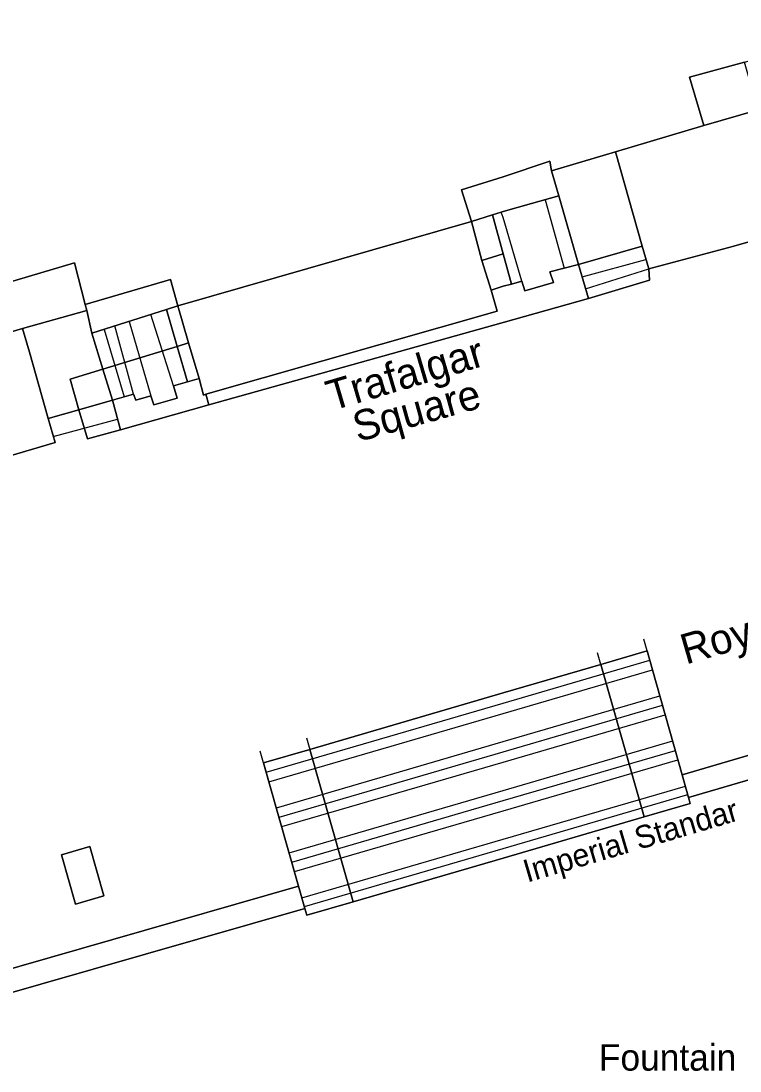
# Model space of a CAD drawing. Extents: x 529240 to 530363, y 179600 to 180767.
# Drawn here: x 529968 to 530015.7, y 180462.4 to 180532 of the extents above; entities that cross this region are included whole.
import ezdxf

# ---------------------------------------------------------------- set-up
doc = ezdxf.new("R2010")
doc.units = 0
for name, color, linetype in [('Building', 7, 'Continuous'), ('General surface', 7, 'Continuous'), ('Path', 7, 'Continuous'), ('Structure', 7, 'Continuous'), ('Unclassified', 7, 'Continuous')]:
    doc.layers.add(name, color=color, linetype=linetype)

msp = doc.modelspace()

# ---------------------------------------------------------------- linework, layer by layer
at = {"layer": 'Building'}
for points in [[(529961.6, 180513), (529971.6, 180515.95), (529972.3, 180513.2), (529977.95, 180514.85), (529978.45, 180513.1), (529997.9, 180518.7), (529997.25, 180520.8), (530000, 180521.65), (530003.1, 180522.7), (530003.2, 180522.05), (530007.45, 180523.3), (530013.3, 180525.05), (530012.35, 180528.25), (530016, 180529.25), (530019.45, 180530.2), (530023.1, 180531.2), (530023.25, 180530.75), (530033.2, 180533.75)], [(530013.3, 180525.05), (530012.35, 180528.25), (530016, 180529.25)], [(530007.45, 180523.3), (530013.3, 180525.05)], [(530003.2, 180522.05), (530007.45, 180523.3)], [(529997.9, 180518.7), (529997.25, 180520.8), (530000, 180521.65), (530003.1, 180522.7), (530003.2, 180522.05)], [(529978.45, 180513.1), (529997.9, 180518.7)], [(529998.6, 180516.1), (529997.9, 180518.7)], [(529961.6, 180513), (529971.6, 180515.95), (529972.3, 180513.2)], [(529999.2, 180514.15), (529998.6, 180516.1)], [(529972.3, 180513.2), (529977.95, 180514.85), (529978.45, 180513.1)], [(529980.3, 180507.25), (529999.6, 180512.75), (529999.2, 180514.15)], [(529972.4, 180512.8), (529972.3, 180513.2)], [(529968.15, 180511.6), (529972.4, 180512.8)], [(529978.45, 180513.1), (529979.15, 180510.65)], [(529962.5, 180509.95), (529968.15, 180511.6)], [(529979.15, 180510.65), (529979.85, 180508.3)], [(529979.85, 180508.3), (529980.15, 180507.2), (529980.3, 180507.25)]]:
    msp.add_lwpolyline(points, dxfattribs=at)
for points in [[(530016, 180529.25), (530012.35, 180528.25), (530013.3, 180525.05), (530016.9, 180526.1)], [(529979.85, 180508.3), (529980.15, 180507.2), (529980.3, 180507.25), (529999.6, 180512.75), (529999.2, 180514.15), (529998.6, 180516.1), (529997.9, 180518.7), (529978.45, 180513.1), (529979.15, 180510.65)], [(529962.5, 180509.95), (529968.15, 180511.6), (529972.4, 180512.8), (529972.3, 180513.2), (529971.6, 180515.95), (529961.6, 180513)], [(529970.73, 180476.74), (529971.66, 180473.47), (529973.53, 180474.02), (529972.6, 180477.29)]]:
    msp.add_lwpolyline(points, close=True, dxfattribs=at)
at = {"layer": 'General surface'}
for points in [[(530009.65, 180515.55), (530015.3, 180517.05), (530019.3, 180518.2), (530016.9, 180526.1), (530013.3, 180525.05), (530007.45, 180523.3), (530009.22, 180517.06)], [(530003.7, 180520.4), (530005, 180515.85), (530009.22, 180517.06), (530007.45, 180523.3), (530003.2, 180522.05)], [(529997.9, 180518.7), (529999.3, 180519.14), (529999.88, 180519.31), (530000, 180519.35), (530001.88, 180519.88), (530003.7, 180520.4), (530003.2, 180522.05), (530003.1, 180522.7), (530000, 180521.65), (529997.25, 180520.8)], [(530000, 180516.55), (530000.55, 180514.55), (530001.25, 180514.75), (530001.45, 180514.1), (530003.35, 180514.65), (530003.1, 180515.35), (530005, 180515.85), (530003.7, 180520.4), (530001.88, 180519.88), (530000, 180519.35), (529999.88, 180519.31), (529999.3, 180519.14)], [(529998.6, 180516.1), (530000, 180516.55), (529999.3, 180519.14), (529997.9, 180518.7)], [(530005, 180515.85), (530005.65, 180513.6), (530009.7, 180514.8), (530009.65, 180515.55), (530009.22, 180517.06)], [(529998.6, 180516.1), (529999.2, 180514.15), (530000, 180514.4), (530000.55, 180514.55), (530000, 180516.55)], [(529999.2, 180514.15), (529999.6, 180512.75), (529980.3, 180507.25), (529980.5, 180506.55), (530000, 180512), (530005.65, 180513.6), (530005, 180515.85), (530003.1, 180515.35), (530003.35, 180514.65), (530001.45, 180514.1), (530001.25, 180514.75), (530000.55, 180514.55), (530000, 180514.4)], [(529977.68, 180512.86), (529978.45, 180513.1), (529977.95, 180514.85), (529972.3, 180513.2), (529972.4, 180512.8), (529972.75, 180511.3)], [(529969.85, 180505.65), (529971.89, 180506.23), (529971.3, 180508.25), (529973.47, 180508.91), (529972.75, 180511.3), (529972.4, 180512.8), (529968.15, 180511.6), (529968.6, 180510.05)], [(529978.39, 180510.42), (529977.68, 180512.86), (529972.75, 180511.3), (529973.47, 180508.91)], [(529978.39, 180510.42), (529979.15, 180510.65), (529978.45, 180513.1), (529977.68, 180512.86)], [(529962.5, 180509.95), (529958.8, 180508.9), (529961.1, 180501.35), (529970.3, 180504.05), (529969.85, 180505.65), (529968.6, 180510.05), (529968.15, 180511.6)], [(529975.5, 180507.25), (529975.65, 180506.85), (529976.65, 180507.15), (529976.85, 180506.55), (529978.4, 180507), (529978.15, 180507.8), (529979.08, 180508.07), (529978.39, 180510.42), (529973.47, 180508.91), (529974.1, 180506.85)], [(529979.15, 180510.65), (529978.39, 180510.42), (529979.08, 180508.07), (529979.85, 180508.3)], [(529974.1, 180506.85), (529973.47, 180508.91), (529971.3, 180508.25), (529971.89, 180506.23)], [(529974.1, 180506.85), (529974.65, 180504.9), (529980.5, 180506.55), (529980.3, 180507.25), (529980.15, 180507.2), (529979.85, 180508.3), (529979.08, 180508.07), (529978.15, 180507.8), (529978.4, 180507), (529976.85, 180506.55), (529976.65, 180507.15), (529975.65, 180506.85), (529975.5, 180507.25)], [(529972.45, 180504.29), (529974.65, 180504.9), (529974.1, 180506.85), (529971.89, 180506.23)], [(530011.88, 180482.04), (530012.3, 180480.54), (530038.35, 180488.15), (530037.95, 180489.7)], [(529971.66, 180473.47), (529973.53, 180474.02), (529972.6, 180477.29), (529970.73, 180476.74)], [(529962.25, 180466.15), (529986.87, 180473.19), (529986.45, 180474.67), (529961.8, 180467.6)]]:
    msp.add_lwpolyline(points, close=True, dxfattribs=at)
for points in [[(530002.78, 180520.14), (530004.05, 180515.6)], [(530003.7, 180520.4), (530005, 180515.85)], [(530001.25, 180514.75), (530000, 180518.95), (529999.88, 180519.31)], [(530019.3, 180518.2), (530015.3, 180517.05), (530009.65, 180515.55), (530009.7, 180514.8), (530005.65, 180513.6), (530000, 180512), (529980.5, 180506.55), (529974.65, 180504.9), (529972.45, 180504.29), (529971.89, 180506.23), (529969.85, 180505.65), (529970.3, 180504.05), (529961.1, 180501.35)], [(530005, 180515.85), (530009.22, 180517.06)], [(530000, 180516.55), (530000.55, 180514.55)], [(530005.24, 180515.03), (530009.47, 180516.17)], [(530005.47, 180514.24), (530009.65, 180515.55)], [(530009.7, 180514.8), (530005.65, 180513.6)], [(529978.15, 180507.8), (529976.66, 180512.53)], [(529977.68, 180512.86), (529978.39, 180510.42)], [(529975.5, 180507.25), (529974.26, 180511.78)], [(529975.21, 180512.08), (529976.65, 180507.15)], [(529972.75, 180511.3), (529973.47, 180508.91)], [(529973.55, 180511.55), (529974.89, 180507.08)], [(529978.39, 180510.42), (529979.08, 180508.07)], [(529973.47, 180508.91), (529974.1, 180506.85)], [(529971.89, 180506.23), (529969.85, 180505.65)], [(529974.1, 180506.85), (529971.89, 180506.23)], [(529970.18, 180504.46), (529974.45, 180505.6)], [(529972.45, 180504.29), (529974.65, 180504.9)], [(529961.8, 180467.6), (529986.45, 180474.67), (529984.48, 180481.59), (529984.12, 180482.84), (529987.19, 180483.73), (530000, 180487.47), (530006.48, 180489.36), (530009.55, 180490.25), (530009.9, 180489), (530011.88, 180482.04), (530037.95, 180489.7)], [(530006.48, 180489.36), (530009.55, 180490.25)], [(529984.3, 180482.22), (530000, 180486.79), (530009.73, 180489.63)], [(529984.48, 180481.59), (530000, 180486.11), (530009.9, 180489)], [(529987.19, 180483.73), (530000, 180487.47), (530006.48, 180489.36)], [(530057.8, 180463.5), (530055.65, 180472), (530053.75, 180479.6), (530051.55, 180488.2), (530041.4, 180485.35), (530039.25, 180484.75), (530038.35, 180488.15), (530012.3, 180480.54), (530012.41, 180480.15), (530009.34, 180479.25), (530000, 180476.53), (529990.07, 180473.64), (529987, 180472.74), (529986.87, 180473.19), (529962.25, 180466.15)], [(529984.97, 180479.86), (530000, 180484.24), (530010.39, 180487.27)], [(529985.15, 180479.24), (530000, 180483.57), (530010.57, 180486.65)], [(529985.33, 180478.61), (530000, 180482.89), (530010.75, 180486.02)], [(529985.82, 180476.88), (530000, 180481.01), (530011.24, 180484.29)], [(529984.12, 180482.84), (529987.19, 180483.73)], [(529986, 180476.26), (530000, 180480.34), (530011.42, 180483.66)], [(529984.12, 180482.84), (529984.3, 180482.22)], [(529986.18, 180475.63), (530000, 180479.65), (530011.59, 180483.03)], [(529984.3, 180482.22), (529984.48, 180481.59)], [(529986.67, 180473.9), (530000, 180477.78), (530012.08, 180481.3)], [(529986.84, 180473.32), (530000, 180477.16), (530012.25, 180480.73)], [(530009.34, 180479.25), (530012.41, 180480.15)], [(529990.07, 180473.64), (530000, 180476.53), (530009.34, 180479.25)], [(529987, 180472.74), (529990.07, 180473.64)]]:
    msp.add_lwpolyline(points, dxfattribs=at)
at = {"layer": 'Path'}
for points in [[(530009.34, 180479.25), (530012.41, 180480.15), (530012.3, 180480.54), (530011.88, 180482.04), (530009.9, 180489), (530009.55, 180490.25), (530006.48, 180489.36)], [(530009.34, 180479.25), (530006.48, 180489.36), (530000, 180487.47), (529987.19, 180483.73), (529990.07, 180473.64), (530000, 180476.53)], [(529984.12, 180482.84), (529984.48, 180481.59), (529986.45, 180474.67), (529986.87, 180473.19), (529987, 180472.74), (529990.07, 180473.64), (529987.19, 180483.73)]]:
    msp.add_lwpolyline(points, close=True, dxfattribs=at)
at = {"layer": 'Unclassified'}
for points in [[(530013.3, 180525.05), (530016.9, 180526.1)], [(530007.45, 180523.3), (530009.22, 180517.06)], [(530003.2, 180522.05), (530003.7, 180520.4)], [(529999.88, 180519.31), (530000, 180519.35), (530001.88, 180519.88), (530003.7, 180520.4)], [(529997.9, 180518.7), (529999.3, 180519.14)], [(529999.3, 180519.14), (529999.88, 180519.31)], [(529999.3, 180519.14), (530000, 180516.55)], [(530019.3, 180518.2), (530015.3, 180517.05), (530009.65, 180515.55)], [(530009.22, 180517.06), (530009.65, 180515.55)], [(529998.6, 180516.1), (530000, 180516.55)], [(530001.25, 180514.75), (530001.45, 180514.1), (530003.35, 180514.65), (530003.1, 180515.35), (530005, 180515.85)], [(530005, 180515.85), (530005.65, 180513.6)], [(530009.65, 180515.55), (530009.7, 180514.8)], [(529999.2, 180514.15), (530000, 180514.4), (530000.55, 180514.55)], [(530000.55, 180514.55), (530001.25, 180514.75)], [(529980.5, 180506.55), (530000, 180512), (530005.65, 180513.6)], [(529972.75, 180511.3), (529972.4, 180512.8)], [(529972.75, 180511.3), (529977.68, 180512.86)], [(529977.68, 180512.86), (529978.45, 180513.1)], [(529968.15, 180511.6), (529968.6, 180510.05), (529969.85, 180505.65)], [(529978.39, 180510.42), (529973.47, 180508.91)], [(529979.15, 180510.65), (529978.39, 180510.42)], [(529973.47, 180508.91), (529971.3, 180508.25), (529971.89, 180506.23)], [(529979.08, 180508.07), (529979.85, 180508.3)], [(529978.15, 180507.8), (529979.08, 180508.07)], [(529978.4, 180507), (529978.15, 180507.8)], [(529974.1, 180506.85), (529975.5, 180507.25)], [(529975.65, 180506.85), (529975.5, 180507.25)], [(529975.65, 180506.85), (529976.65, 180507.15)], [(529976.65, 180507.15), (529976.85, 180506.55)], [(529976.85, 180506.55), (529978.4, 180507)], [(529980.3, 180507.25), (529980.5, 180506.55)], [(529971.89, 180506.23), (529972.45, 180504.29)], [(529974.65, 180504.9), (529974.1, 180506.85)], [(529974.65, 180504.9), (529980.5, 180506.55)], [(529961.1, 180501.35), (529970.3, 180504.05), (529969.85, 180505.65)], [(530009.55, 180490.25), (530009.33, 180491.02)], [(530009.9, 180489), (530009.55, 180490.25)], [(530006.48, 180489.36), (530006.26, 180490.12)], [(530011.88, 180482.04), (530037.95, 180489.7)], [(530009.34, 180479.25), (530006.48, 180489.36)], [(530011.88, 180482.04), (530009.9, 180489)], [(530038.35, 180488.15), (530012.3, 180480.54)], [(529986.97, 180484.5), (529987.19, 180483.73)], [(529984.12, 180482.84), (529983.9, 180483.61)], [(529987.19, 180483.73), (529990.07, 180473.64)], [(529984.48, 180481.59), (529984.12, 180482.84)], [(530012.3, 180480.54), (530011.88, 180482.04)], [(529986.45, 180474.67), (529984.48, 180481.59)], [(530012.41, 180480.15), (530012.3, 180480.54)], [(529970.73, 180476.74), (529972.6, 180477.29), (529973.53, 180474.02), (529971.66, 180473.47), (529970.73, 180476.74)], [(529961.8, 180467.6), (529986.45, 180474.67)], [(529986.87, 180473.19), (529986.45, 180474.67)], [(529962.25, 180466.15), (529986.87, 180473.19)], [(529987, 180472.74), (529986.87, 180473.19)]]:
    msp.add_lwpolyline(points, dxfattribs=at)

# ---------------------------------------------------------------- texts
at = {"layer": 'General surface'}
for s, height, rotation, p in [('Trafalgar', 2, 16.5, (529988.64, 180506.14)), ('Square', 2, 15.5, (529990.37, 180504.08)), ('Imperial Standar', 1.5, 16.4, (530001.6, 180474.9))]:
    msp.add_text(s, height=height, rotation=rotation, dxfattribs=at).set_placement(p)
at = {"layer": 'Structure'}
msp.add_text('Fountain', height=1.75, dxfattribs=at).set_placement((530006.35, 180462.45))
at = {"layer": 'Unclassified'}
msp.add_text('Royal Mews', height=2, rotation=16.1, dxfattribs=at).set_placement((530012.11, 180489.34))

doc.saveas('drawing.dxf')
